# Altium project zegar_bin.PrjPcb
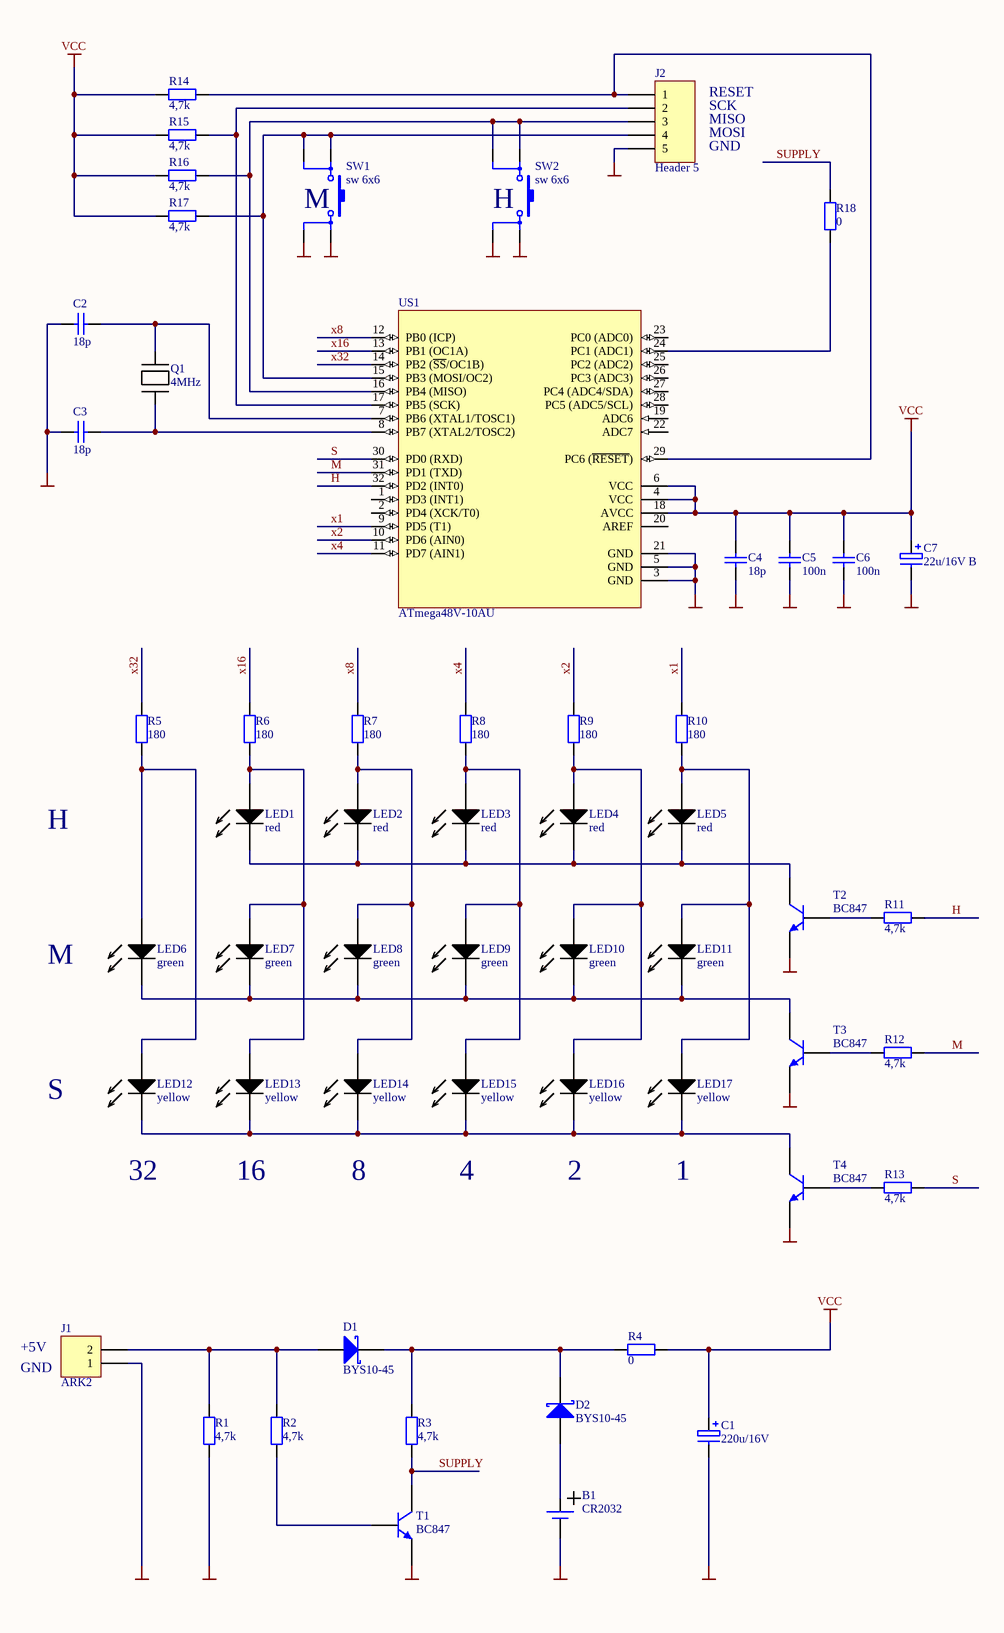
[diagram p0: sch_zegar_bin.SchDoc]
1 sheet, 55 parts. Net scope: global (net labels, ports and power ports of the same name join across sheets).
Board file: pcb_zegar_bin.PcbDoc

## Sheet sch_zegar_bin.SchDoc
size A2

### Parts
B1  CR2032  [CR20xx THT]
C1  220u/16V  [2,5/7mm le抗cy elektrolit]
C2  18p  [MELF-1206]
C3  18p  [MELF-1206]
C4  18p  [MELF-1206]
C5  100n  [MELF-1206]
C6  100n  [MELF-1206]
C7  22u/16V B  [Tantal B 3528-1411]
D1  BYS10-45  [SMA]
D2  BYS10-45  [SMA]
J1  ARK2  [ARK2 5mm]
J2  Header 5  [HDR1X5]
LED1  red  [LED 5mm]
LED2  red  [LED 5mm]
LED3  red  [LED 5mm]
LED4  red  [LED 5mm]
LED5  red  [LED 5mm]
LED6  green  [LED 5mm]
LED7  green  [LED 5mm]
LED8  green  [LED 5mm]
LED9  green  [LED 5mm]
LED10  green  [LED 5mm]
LED11  green  [LED 5mm]
LED12  yellow  [LED 5mm]
LED13  yellow  [LED 5mm]
LED14  yellow  [LED 5mm]
LED15  yellow  [LED 5mm]
LED16  yellow  [LED 5mm]
LED17  yellow  [LED 5mm]
Q1  4MHz  [kwarc 5mm]
R1  4,7k  [MELF-1206]
R2  4,7k  [MELF-1206]
R3  4,7k  [MELF-1206]
R4  0  [MELF-1206]
R5  180  [MELF-1206]
R6  180  [MELF-1206]
R7  180  [MELF-1206]
R8  180  [MELF-1206]
R9  180  [MELF-1206]
R10  180  [MELF-1206]
R11  4,7k  [MELF-1206]
R12  4,7k  [MELF-1206]
R13  4,7k  [MELF-1206]
R14  4,7k  [MELF-1206]
R15  4,7k  [MELF-1206]
R16  4,7k  [MELF-1206]
R17  4,7k  [MELF-1206]
R18  0  [MELF-1206]
SW1  sw 6x6  [tact switch 6x6]
SW2  sw 6x6  [tact switch 6x6]
T1  BC847  [318-08]
T2  BC847  [318-08]
T3  BC847  [318-08]
T4  BC847  [318-08]
US1  ATmega48V-10AU  [32A_N]

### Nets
GND: B1.2(-) C1.2 C2.1 C3.1 C4.1 C5.1 C6.1 C7.2 J1.1 J2.5 R1.1 SW1.2 SW1.4 SW2.2 SW2.4 T1.2(E) T2.2(E) T3.2(E) T4.2(E) US1.3(GND) US1.5(GND) US1.21(GND)
VCC: C1.1 C4.2 C5.2 C6.2 C7.1 R4.1 R14.2 R15.2 R16.2 R17.2 US1.4(VCC) US1.6(VCC) US1.18(AVCC)
H: R11.2 US1.32(PD2_(INT0))
M: R12.2 US1.31(PD1_(TXD))
S: R13.2 US1.30(PD0_(RXD))
SUPPLY: R3.1 R18.1 T1.3(C)
x1: R10.2 US1.9(PD5_(T1))
x2: R9.2 US1.10(PD6_(AIN0))
x4: R8.2 US1.11(PD7_(AIN1))
x8: R7.2 US1.12(PB0_(ICP))
x16: R6.2 US1.13(PB1_(OC1A))
x32: R5.2 US1.14(PB2_(~{SS}/OC1B))
NetB1_1: B1.1(+) D2.1(A)
NetC2_2: C2.2 Q1.2 US1.7(PB6_(XTAL1/TOSC1))
NetC3_2: C3.2 Q1.1 US1.8(PB7_(XTAL2/TOSC2))
NetD1_1: D1.1(A) J1.2 R1.2 R2.2
NetD1_2: D1.2(K) D2.2(K) R3.2 R4.2
NetJ2_1: J2.1 R14.1 US1.29(PC6_(~{RESET}))
NetJ2_2: J2.2 R15.1 US1.17(PB5_(SCK))
NetJ2_3: J2.3 R16.1 SW2.1 SW2.3 US1.16(PB4_(MISO))
NetJ2_4: J2.4 R17.1 SW1.1 SW1.3 US1.15(PB3_(MOSI/OC2))
NetLED1_A: LED1.A LED7.A LED13.A R6.1
NetLED1_K: LED1.K LED2.K LED3.K LED4.K LED5.K T2.3(C)
NetLED2_A: LED2.A LED8.A LED14.A R7.1
NetLED3_A: LED3.A LED9.A LED15.A R8.1
NetLED4_A: LED4.A LED10.A LED16.A R9.1
NetLED5_A: LED5.A LED11.A LED17.A R10.1
NetLED6_A: LED6.A LED12.A R5.1
NetLED6_K: LED6.K LED7.K LED8.K LED9.K LED10.K LED11.K T3.3(C)
NetLED12_K: LED12.K LED13.K LED14.K LED15.K LED16.K LED17.K T4.3(C)
NetR2_1: R2.1 T1.1(B)
NetR11_1: R11.1 T2.1(B)
NetR12_1: R12.1 T3.1(B)
NetR13_1: R13.1 T4.1(B)
NetR18_2: R18.2 US1.24(PC1_(ADC1))

Not connected (* = marked no-connect by the designer): US1 1(PD3_(INT1)) 2(PD4_(XCK/T0)) 19(ADC6) 20(AREF) 22(ADC7) 23(PC0_(ADC0)) 25(PC2_(ADC2)) 26(PC3_(ADC3)) 27(PC4_(ADC4/SDA)) 28(PC5_(ADC5/SCL))

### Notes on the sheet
- RESET
- SCK
- MISO
- MOSI
- GND
- (near SW1) M
- (near SW2) H
- H
- M
- S
- 32
- 16
- 8
- 4
- 2
- 1
- +5V

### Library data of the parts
B1 = BAT
C1 C7 = kond biegunowy: Polarized Capacitor
C2-C4 = kondensator: Value: 100n
C5 C6 = kondensator
D1 D2 = 10MQ060N: Schottky Rectifier; PackageDocument: revH, May-2002
J2 = Header 5: Header, 5-Pin
LED1-LED17 = LED
Q1 = kwarc
R1-R18 = rezystor
SW1 SW2 = switch
T1-T4 = BC847ALT1: General Purpose Transistor NPN Silicon
US1 = ATmega8-16AC: 8-Bit AVR Microcontroller with 8K Bytes of In-System Programmable Flash Memory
